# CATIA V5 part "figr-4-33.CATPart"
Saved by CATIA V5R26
Part number: Part1
Bounding box of the stored display mesh (mm): x 0 to 81, y 0 to 160, z -80 to 0
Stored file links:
  D:\_Deepak\CATIA\CATIA V5-6R2016_Deepak\Resources\Part files\Partfiles\c04_catia_v5_6r2016_prt\figr-4-33.CATPart
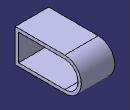
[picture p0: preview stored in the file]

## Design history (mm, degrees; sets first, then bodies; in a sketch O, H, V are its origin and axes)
Body1 (main body)
  Sketch1 on yz-plane, origin (0, 0, 0), H (0, 1, 0), V (0, 0, 1)
    line L1 (0, 0) -> (0, -80)
    line L2 (0, -80) -> (120, -80)
    arc A1 centre (120, -40) radius 40 from (120, -80) to (120, 0) ccw
    line L3 (120, 0) -> (0, 0)
    tangency: A1 L2
  Pad1: profile Sketch1, direction (1, 0, 0), length 81, thin wall 8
